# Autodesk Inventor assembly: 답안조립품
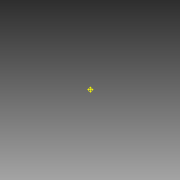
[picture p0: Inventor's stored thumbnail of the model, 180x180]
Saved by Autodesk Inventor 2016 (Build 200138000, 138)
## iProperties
Created: 2018-08
Part Number: 답안조립품
Document SubType Name: Assembly
Designer: MIRAE
Author: MIRAE
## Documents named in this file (14)
- C:\Users\MIRAE\Desktop\480807V1029\답안조립품.iam
- C:\Users\MIRAE\Desktop\480807V1029\본체.ipt
- C:\Users\MIRAE\Desktop\480807V1029\메인 베벨기어.ipt
- C:\Users\MIRAE\Desktop\480807V1029\메인 축.ipt
- 메인 축.ipt
- C:\Users\MIRAE\Desktop\480807V1029\베어링 6203.ipt
- C:\Users\MIRAE\Desktop\480807V1029\볼트 M4.ipt
- C:\Users\MIRAE\Desktop\480807V1029\서브 베벨기어.ipt
- C:\Users\MIRAE\Desktop\480807V1029\서브 축.ipt
- 서브 축.ipt
- C:\Users\MIRAE\Desktop\480807V1029\오일실 17 32 8.ipt
- C:\Users\MIRAE\Desktop\480807V1029\커버.ipt
- C:\Users\MIRAE\Desktop\480807V1029\키 4x4.ipt
- C:\Users\MIRAE\Desktop\480807V1029\키 5x5.ipt
## Component patterns: 구성요소 패턴 1:2 (4 elements), 구성요소 패턴 1:3 (4 elements), 구성요소 패턴 1:4 (4 elements)
